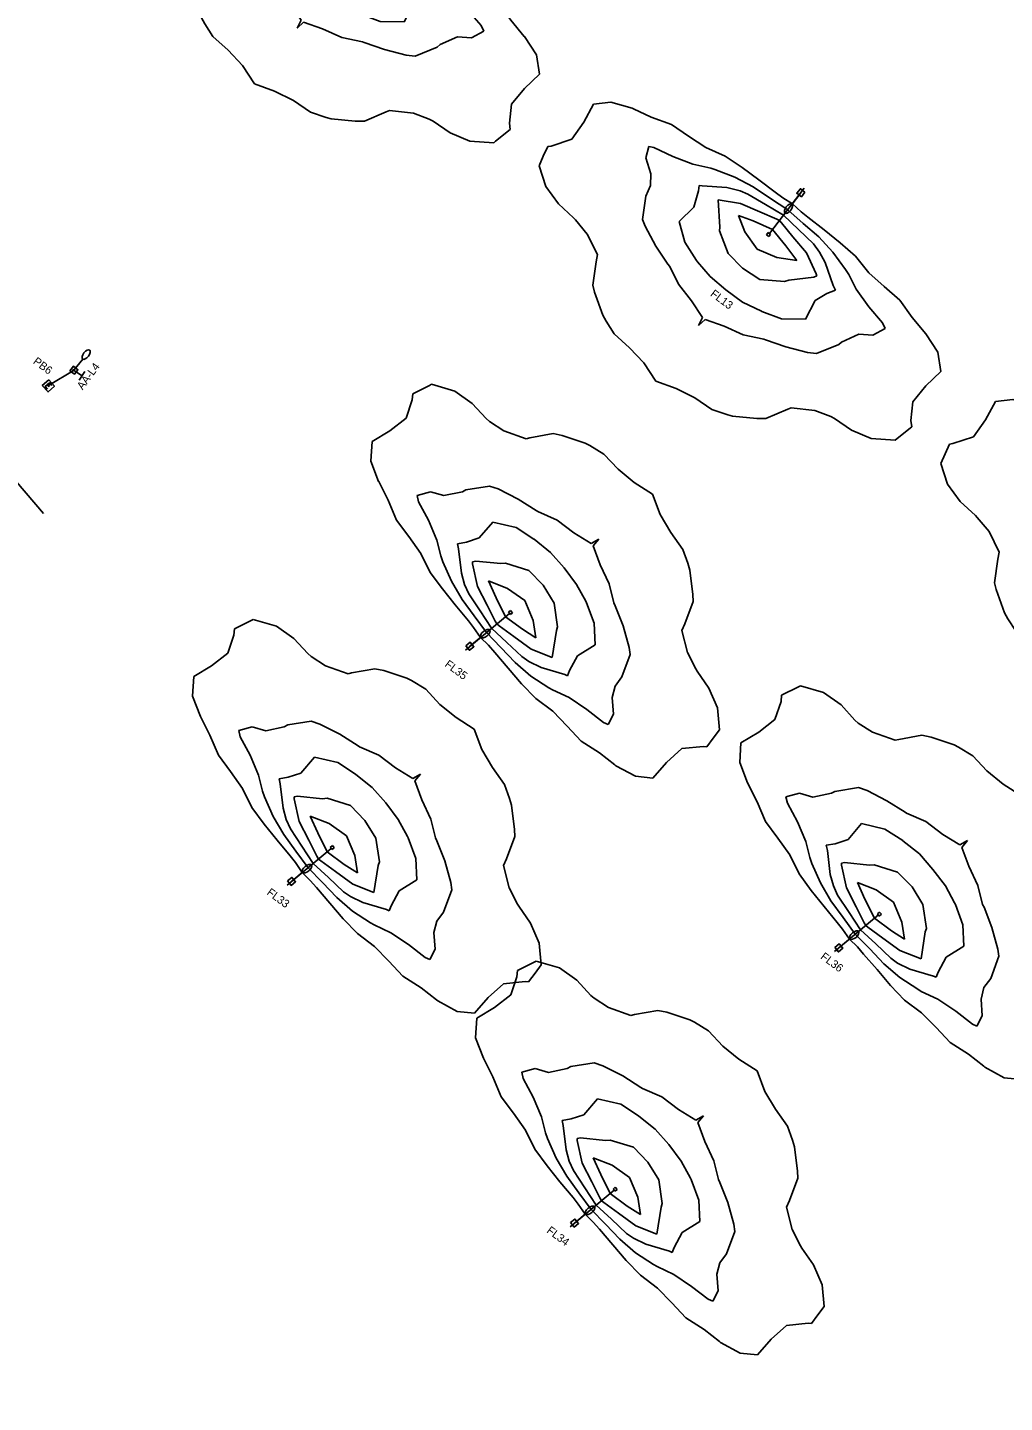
# Model space of a CAD drawing. Extents: x 1322666 to 1327584, y 458075 to 462260.
# Drawn here: x 1324729.9 to 1325071.8, y 459883.3 to 460364.4 of the extents above; entities that cross this region are included whole.
import ezdxf

# ---------------------------------------------------------------- set-up
doc = ezdxf.new("R2010")
doc.units = 0
for name, color, linetype in [('_CIVIL_CONSTRUCTION', 7, 'Continuous'), ('Default', 7, 'Continuous'), ('DR_P_Culvert', 7, 'Continuous'), ('DR_P_Culvert3D', 7, 'Continuous'), ('DR_X_Cells', 7, 'Continuous'), ('UT_X_Cable_TV_FO', 7, 'Continuous'), ('UT_X_Misc_Cells', 7, 'Continuous'), ('UT_X_Oil', 7, 'Continuous')]:
    doc.layers.add(name, color=color, linetype=linetype)

# ---------------------------------------------------------------- blocks, each defined once
blk = doc.blocks.new('AGI32-IDj66arb-Project_1-LUMINAIRE-ERL2_19C330______Symbol')
at = {"layer": 'Default'}
for p, q in [((-0.03, 0), (0.03, 0)), ((0, 0.13), (0.24, 0.13)), ((0, -0.13), (0, 0.13)), ((0, 0.13), (0, 0.13)), ((0, 0.13), (0.24, 0.13)), ((0.24, 0.13), (0, 0.13)), ((0, -0.13), (0, 0.13)), ((0, 0.13), (0, 0.13)), ((0, 0.13), (0, -0.13)), ((0.24, 0.13), (0, 0.13)), ((0, 0.13), (0, -0.13)), ((0, -0.03), (0, 0.03)), ((0, 0.03), (0.03, 0)), ((0, -0.03), (0.03, 0)), ((0.24, 0.13), (0.24, -0.13)), ((0.24, 0.13), (0.24, 0.13)), ((0.24, 0.13), (0.24, 0.13)), ((0.24, 0.13), (0.24, -0.13)), ((0.24, -0.13), (0.24, 0.13)), ((0.24, -0.13), (0.24, 0.13)), ((0.24, -0.13), (0, -0.13)), ((0.24, -0.13), (0, -0.13)), ((0, -0.13), (0, -0.13)), ((0, -0.13), (0.24, -0.13)), ((0, -0.13), (0, -0.13)), ((0, -0.13), (0.24, -0.13)), ((0.24, -0.13), (0.24, -0.13)), ((0.24, -0.13), (0.24, -0.13))]:
    blk.add_line(p, q, dxfattribs=at)
blk = doc.blocks.new('AGI32-IDj66arb-Project_1-LUMINAIRE-ERL2_19C330______64-1')
at = {"layer": 'Default'}
blk.add_blockref('AGI32-IDj66arb-Project_1-LUMINAIRE-ERL2_19C330______Symbol', (0, 0), dxfattribs=at)
blk = doc.blocks.new('AGI32-IDj66arb-Project_1-LUMINAIRE-ERL2_19C330______Template1')
at = {"layer": 'Default'}
for p, q in [((4.29, 18.29), (5.49, 19.56)), ((5.49, 19.56), (7.31, 19.28)), ((9.14, 19.22), (10.58, 20.11)), ((10.58, 20.11), (10.97, 20.5)), ((10.97, 20.5), (12.6, 20.11)), ((12.6, 20.11), (12.8, 20.07)), ((12.8, 20.07), (13.99, 18.29)), ((7.31, 19.28), (9.14, 19.22)), ((3.66, 16.46), (4.29, 18.29)), ((13.99, 18.29), (14.48, 16.46)), ((3.25, 14.63), (3.66, 16.45)), ((3.66, 16.45), (3.66, 16.46)), ((14.48, 16.46), (14.57, 14.63)), ((2.69, 12.8), (3.25, 14.63)), ((14.57, 14.63), (14.63, 14.24)), ((14.63, 14.24), (15.08, 12.8)), ((2.59, 10.97), (2.69, 12.8)), ((4.85, 10.97), (5.23, 12.8)), ((5.23, 12.8), (5.49, 13.32)), ((5.49, 13.32), (6.62, 12.8)), ((6.62, 12.8), (7.31, 11.77)), ((15.08, 12.8), (16.17, 10.97)), ((7.31, 11.77), (8.8, 10.97)), ((2.44, 9.14), (2.59, 10.97)), ((4.29, 9.14), (4.85, 10.97)), ((8.8, 10.97), (9.14, 10.91)), ((9.14, 10.91), (10.97, 9.83)), ((10.97, 9.83), (11.39, 9.14)), ((16.17, 10.97), (16.46, 10.82)), ((16.46, 10.82), (18.29, 9.79)), ((18.29, 9.79), (18.8, 9.14)), ((2, 7.31), (2.44, 9.14)), ((3.66, 7.83), (4.29, 9.14)), ((11.39, 9.14), (12.17, 7.31)), ((18.8, 9.14), (19.94, 7.31)), ((3.47, 7.31), (3.66, 7.83)), ((5.27, 7.31), (5.49, 7.72)), ((5.49, 7.72), (6.19, 7.31)), ((1.89, 5.49), (2, 7.31)), ((2.95, 5.49), (3.47, 7.31)), ((4.09, 5.49), (5.27, 7.31)), ((6.19, 7.31), (7.31, 6.87)), ((7.31, 6.87), (9.14, 7.19)), ((9.14, 7.19), (10.42, 5.49)), ((12.17, 7.31), (12.76, 5.49)), ((19.94, 7.31), (20.11, 6.9)), ((20.11, 6.9), (20.59, 5.49)), ((1.86, 3.66), (1.89, 5.49)), ((2.64, 3.66), (2.95, 5.49)), ((3.66, 4.54), (4.09, 5.49)), ((4.43, 3.66), (5.39, 5.49)), ((5.39, 5.49), (5.49, 5.63)), ((5.49, 5.63), (5.75, 5.49)), ((5.75, 5.49), (7.31, 3.9)), ((10.42, 5.49), (10.97, 3.69)), ((12.76, 5.49), (12.8, 5.34)), ((12.8, 5.34), (13.64, 3.66)), ((20.59, 5.49), (20.69, 3.66)), ((3.42, 3.66), (3.66, 4.54)), ((7.31, 3.9), (7.65, 3.66)), ((10.97, 3.69), (10.98, 3.66)), ((1.85, 1.83), (1.86, 3.66)), ((2.53, 1.83), (2.64, 3.66)), ((3.22, 1.83), (3.42, 3.66)), ((4.03, 1.83), (4.43, 3.66)), ((5.05, 1.83), (5.49, 3.41)), ((5.49, 3.41), (6.36, 1.83)), ((7.65, 3.66), (8.83, 1.83)), ((10.98, 3.66), (11.36, 1.83)), ((13.64, 3.66), (14.06, 1.83)), ((20.69, 3.66), (21.05, 1.83)), ((1.83, 1.08), (1.85, 1.83)), ((2.41, 0), (2.53, 1.83)), ((3.01, 0), (3.22, 1.83)), ((3.66, 0.28), (4.03, 1.83)), ((4.62, 0), (5.05, 1.83)), ((6.36, 1.83), (6.85, 0)), ((8.83, 1.83), (8.98, 0)), ((11.36, 1.83), (11.4, 0)), ((14.06, 1.83), (14.63, 0.14)), ((21.05, 1.83), (21.63, 0)), ((1.73, 0), (1.83, 1.08)), ((3.62, 0), (3.66, 0.28)), ((14.63, 0.14), (15.4, 0)), ((1.83, -0.98), (1.73, 0)), ((1.85, -1.83), (1.83, -0.98)), ((2.55, -1.83), (2.41, 0)), ((3.25, -1.83), (3.01, 0)), ((3.66, -0.25), (3.62, 0)), ((4.07, -1.83), (3.66, -0.25)), ((5.07, -1.83), (4.62, 0)), ((6.85, 0), (6.29, -1.83)), ((8.98, 0), (8.72, -1.83)), ((11.4, 0), (11.31, -1.83)), ((14.63, -0.15), (14.04, -1.83)), ((15.4, 0), (14.63, -0.15)), ((21.63, 0), (20.99, -1.83)), ((1.88, -3.66), (1.85, -1.83)), ((2.67, -3.66), (2.55, -1.83)), ((3.47, -3.66), (3.25, -1.83)), ((4.53, -3.66), (4.07, -1.83)), ((5.49, -3.15), (5.07, -1.83)), ((6.29, -1.83), (5.49, -3.15)), ((8.72, -1.83), (7.6, -3.66)), ((11.31, -1.83), (10.97, -3.51)), ((14.04, -1.83), (13.56, -3.66)), ((20.99, -1.83), (20.7, -3.66)), ((1.89, -5.49), (1.88, -3.66)), ((2.97, -5.49), (2.67, -3.66)), ((3.66, -4.38), (3.47, -3.66)), ((5.49, -5.44), (4.53, -3.66)), ((7.6, -3.66), (7.31, -3.83)), ((10.94, -3.66), (10.29, -5.49)), ((10.97, -3.51), (10.94, -3.66)), ((13.56, -3.66), (12.8, -5.21)), ((20.7, -3.66), (20.55, -5.49)), ((4.15, -5.49), (3.66, -4.38)), ((7.31, -3.83), (5.49, -5.44)), ((2.03, -7.31), (1.89, -5.49)), ((3.54, -7.31), (2.97, -5.49)), ((5.37, -7.31), (4.15, -5.49)), ((10.29, -5.49), (9.14, -7.01)), ((12.73, -5.49), (12.12, -7.31)), ((12.8, -5.21), (12.73, -5.49)), ((20.55, -5.49), (20.11, -6.73)), ((2.46, -9.14), (2.03, -7.31)), ((3.66, -7.66), (3.54, -7.31)), ((5.49, -7.55), (5.37, -7.31)), ((5.91, -7.31), (5.49, -7.55)), ((7.31, -6.76), (5.91, -7.31)), ((9.14, -7.01), (7.31, -6.76)), ((12.12, -7.31), (11.3, -9.14)), ((19.86, -7.31), (18.68, -9.14)), ((20.11, -6.73), (19.86, -7.31)), ((4.35, -9.14), (3.66, -7.66)), ((2.61, -10.97), (2.46, -9.14)), ((4.89, -10.97), (4.35, -9.14)), ((10.97, -9.68), (9.14, -10.74)), ((11.3, -9.14), (10.97, -9.68)), ((18.29, -9.64), (16.46, -10.68)), ((18.68, -9.14), (18.29, -9.64)), ((2.71, -12.8), (2.61, -10.97)), ((5.29, -12.8), (4.89, -10.97)), ((8.15, -10.97), (7.31, -11.59)), ((9.14, -10.74), (8.15, -10.97)), ((15.87, -10.97), (14.99, -12.8)), ((16.46, -10.68), (15.87, -10.97)), ((7.31, -11.59), (6.44, -12.8)), ((3.3, -14.63), (2.71, -12.8)), ((5.49, -13.2), (5.29, -12.8)), ((6.44, -12.8), (5.49, -13.2)), ((14.99, -12.8), (14.63, -14.39)), ((3.66, -16.33), (3.3, -14.63)), ((14.6, -14.63), (14.44, -16.46)), ((14.63, -14.39), (14.6, -14.63)), ((3.68, -16.46), (3.66, -16.33)), ((4.41, -18.29), (3.68, -16.46)), ((14.44, -16.46), (13.9, -18.29)), ((5.49, -19.4), (4.41, -18.29)), ((13.9, -18.29), (12.8, -19.89)), ((7.31, -19.11), (5.49, -19.4)), ((9.14, -19.03), (7.31, -19.11)), ((10.75, -20.11), (9.14, -19.03)), ((10.97, -20.33), (10.75, -20.11)), ((11.9, -20.11), (10.97, -20.33)), ((12.8, -19.89), (11.9, -20.11))]:
    blk.add_line(p, q, dxfattribs=at)
blk = doc.blocks.new('AGI32-IDj66arb-Project_1-LUMINAIRE-ERL2_19C330______64')
at = {"layer": 'Default'}
for q in [(5.08, 0), (0, 0)]:
    blk.add_line((0, 0), q, dxfattribs=at)
for name, p in [('AGI32-IDj66arb-Project_1-LUMINAIRE-ERL2_19C330______Template1', (0, 0)), ('AGI32-IDj66arb-Project_1-LUMINAIRE-ERL2_19C330______64-1', (5.08, 0))]:
    blk.add_blockref(name, p, dxfattribs=at)

msp = doc.modelspace()

# ---------------------------------------------------------------- linework, layer by layer
at = {"layer": '_CIVIL_CONSTRUCTION'}
msp.add_line((1324746.12, 460244.47), (1324749.21, 460248.4), dxfattribs=at)
msp.add_lwpolyline([(1324744.72, 460244.29), (1324745.95, 460245.87), (1324747.53, 460244.64), (1324746.29, 460243.06)], close=True, dxfattribs=at)
msp.add_ellipse((1324750.44, 460249.97), major_axis=(1.23, 1.57), ratio=0.5, dxfattribs=at)
at = {"layer": 'DR_P_Culvert'}
for p, q in [((1325000.53, 460306.57), (1324997.45, 460302.63)), ((1324884.71, 460147.89), (1324888.57, 460151.07)), ((1324822.32, 460065.64), (1324826.18, 460068.82)), ((1325013.79, 460042.39), (1325017.66, 460045.56)), ((1324921.35, 459946.09), (1324925.21, 459949.26))]:
    msp.add_line(p, q, dxfattribs=at)
for points in [[(1325001.93, 460306.74), (1325000.7, 460305.16), (1324999.12, 460306.39), (1325000.35, 460307.97)], [(1324883.3, 460148.03), (1324884.85, 460149.3), (1324886.12, 460147.76), (1324884.57, 460146.49)], [(1324820.91, 460065.78), (1324822.45, 460067.05), (1324823.72, 460065.51), (1324822.18, 460064.24)], [(1325012.39, 460042.53), (1325013.93, 460043.8), (1325015.2, 460042.25), (1325013.66, 460040.98)], [(1324919.94, 459946.23), (1324921.48, 459947.5), (1324922.75, 459945.95), (1324921.21, 459944.68)]]:
    msp.add_lwpolyline(points, close=True, dxfattribs=at)
for centre, major_axis in [((1324996.22, 460301.05), (-1.23, -1.58)), ((1324890.12, 460152.34), (1.55, 1.27)), ((1324827.72, 460070.09), (1.55, 1.27)), ((1325019.2, 460046.83), (1.55, 1.27)), ((1324926.75, 459950.53), (1.55, 1.27))]:
    msp.add_ellipse(centre, major_axis=major_axis, ratio=0.5, dxfattribs=at)
at = {"layer": 'DR_P_Culvert3D'}
msp.add_lwpolyline([(1323769.14, 461021), (1323830.68, 460971.15), (1323902.43, 460913.55), (1324025.79, 460817.22), (1324184.37, 460693.72), (1324247.58, 460644), (1324302.39, 460600.37), (1324345.59, 460566.06), (1324422.31, 460505.74), (1324432.36, 460498.2), (1324443.79, 460488.66), (1324451.71, 460481.87), (1324470.52, 460465.4), (1324491.64, 460446.42), (1324531.14, 460408.67), (1324575.16, 460365.41), (1324616.32, 460324.05), (1324657.82, 460282.32), (1324698.81, 460237.16), (1324735.51, 460194.32)], dxfattribs=at)
at = {"layer": 'DR_X_Cells'}
msp.add_line((1324736.81, 460239.45), (1324737.48, 460238.71), dxfattribs=at)
msp.add_lwpolyline([(1324737.3, 460241.13), (1324739.31, 460238.91), (1324737.09, 460236.89), (1324735.08, 460239.12)], close=True, dxfattribs=at)
msp.add_lwpolyline([(1324738.39, 460239.2), (1324737.55, 460240.12), (1324736.07, 460238.78), (1324736.91, 460237.85)], dxfattribs=at)
at = {"layer": 'UT_X_Cable_TV_FO'}
msp.add_line((1324737.22, 460239.1), (1324746.24, 460244.54), dxfattribs=at)
at = {"layer": 'UT_X_Oil'}
for p, q in [((1324745.66, 460244.74), (1324749.04, 460242.57)), ((1324748.02, 460240.98), (1324749.98, 460244.02))]:
    msp.add_line(p, q, dxfattribs=at)

# ---------------------------------------------------------------- block references
at = {"layer": 'DR_P_Culvert'}
for p, xscale, yscale, rotation in [((1325069.37, 460453.42), 3.9370000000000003, 3.9369999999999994, -108.74000354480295), ((1324861.23, 460412.2), 3.9370000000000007, 3.9370000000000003, -127.5957929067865), ((1325001.71, 460308.16), 3.9370000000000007, 3.9370000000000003, -127.5957929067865), ((1324883.21, 460146.59), 3.937, 3.9370000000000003, 39.81756765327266), ((1325142.31, 460204.03), 3.9370000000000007, 3.9370000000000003, -127.5957929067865), ((1324820.81, 460064.34), 3.937, 3.9370000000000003, 39.81756765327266), ((1325012.29, 460041.09), 3.937, 3.9370000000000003, 39.81756765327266), ((1324919.84, 459944.79), 3.937, 3.9370000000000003, 39.81756765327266)]:
    msp.add_blockref('AGI32-IDj66arb-Project_1-LUMINAIRE-ERL2_19C330______64', p, dxfattribs=dict(at, xscale=xscale, yscale=yscale, rotation=rotation))

# ---------------------------------------------------------------- texts
at = {"layer": 'UT_X_Misc_Cells'}
for s, rotation, p in [('FL13', 323.4759, (1324968.62, 460270.69)), ('PB6', 323.4759, (1324731.61, 460247.04)), ('AA-L4', 53.4759, (1324749.18, 460237.41)), ('FL35', 323.4759, (1324875.68, 460141.08)), ('FL33', 323.4759, (1324813.4, 460061.25)), ('FL36', 323.4759, (1325007.17, 460038.78)), ('FL34', 323.4759, (1324911.35, 459942.96))]:
    msp.add_text(s, height=2.8, rotation=rotation, dxfattribs=at).set_placement(p)

doc.saveas('drawing.dxf')
